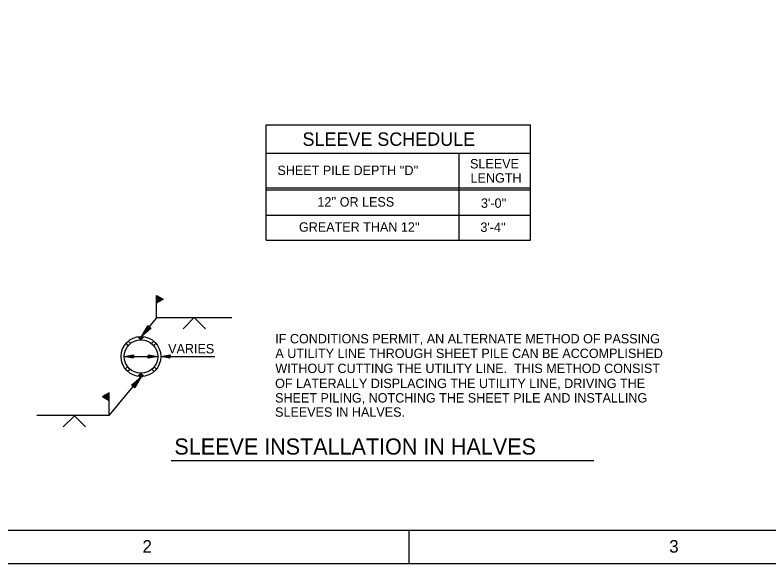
# Model space of a CAD drawing. Extents: x 22339.2 to 22413.4, y 22369.6 to 22418.8.
# Drawn here: x 22369.8 to 22384.77, y 22369.62 to 22380.52 of the extents above; entities that cross this region are included whole.
import ezdxf

# ---------------------------------------------------------------- set-up
doc = ezdxf.new("R2010")
doc.units = 0
for name, color, linetype in [('Level 1', 7, 'Continuous'), ('Level 10', 7, 'Continuous'), ('Level 2', 7, 'Continuous'), ('Level 3', 7, 'Continuous'), ('Level 4', 7, 'Continuous'), ('Level 7', 7, 'Continuous'), ('Level 9', 7, 'Continuous')]:
    doc.layers.add(name, color=color, linetype=linetype)

msp = doc.modelspace()

# ---------------------------------------------------------------- linework, layer by layer
at = {"layer": 'Level 1'}
for p, q in [((22372.31, 22374.139), (22372.31, 22374.139)), ((22372.354, 22374.192), (22372.354, 22374.192)), ((22372.048, 22373.96), (22372.003, 22374.005)), ((22372.093, 22374.003), (22372.048, 22374.048)), ((22372.507, 22374.001), (22372.552, 22374.045)), ((22372.552, 22373.957), (22372.597, 22374.002)), ((22371.965, 22373.741), (22372.632, 22373.741)), ((22371.965, 22373.741), (22371.965, 22373.741)), ((22372.017, 22373.741), (22372.017, 22373.741)), ((22372.58, 22373.741), (22372.58, 22373.741)), ((22372.632, 22373.741), (22372.632, 22373.741)), ((22372.695, 22373.741), (22373.768, 22373.741)), ((22372.695, 22373.741), (22372.695, 22373.741)), ((22372.747, 22373.741), (22372.747, 22373.741)), ((22371.989, 22373.495), (22372.033, 22373.539)), ((22372.032, 22373.449), (22372.076, 22373.493)), ((22372.562, 22373.446), (22372.518, 22373.49)), ((22372.605, 22373.491), (22372.561, 22373.535)), ((22372.301, 22373.339), (22372.301, 22373.339)), ((22372.257, 22373.286), (22372.257, 22373.286))]:
    msp.add_line(p, q, dxfattribs=at)
msp.add_lwpolyline([(22354.719, 22414.965), (22413.386, 22414.965), (22413.386, 22369.621), (22354.719, 22369.621)], close=True, dxfattribs=at)
for points in [[(22372.152, 22373.71), (22371.965, 22373.741), (22372.152, 22373.772), (22372.152, 22373.719), (22372.017, 22373.741), (22372.144, 22373.762), (22372.144, 22373.728), (22372.067, 22373.741), (22372.136, 22373.752), (22372.136, 22373.738), (22372.119, 22373.741)], [(22372.445, 22373.772), (22372.632, 22373.741), (22372.445, 22373.71), (22372.445, 22373.763), (22372.58, 22373.741), (22372.453, 22373.72), (22372.453, 22373.754), (22372.53, 22373.741), (22372.461, 22373.73), (22372.461, 22373.744), (22372.478, 22373.741)], [(22372.882, 22373.71), (22372.695, 22373.741), (22372.882, 22373.772), (22372.882, 22373.719), (22372.747, 22373.741), (22372.874, 22373.762), (22372.874, 22373.728), (22372.797, 22373.741), (22372.866, 22373.752), (22372.866, 22373.738), (22372.849, 22373.741)]]:
    msp.add_lwpolyline(points, dxfattribs=at)
at = {"layer": 'Level 10'}
for p, q in [((22372.611, 22374.504), (22372.611, 22374.954)), ((22372.611, 22374.954), (22372.741, 22374.879)), ((22372.741, 22374.879), (22372.611, 22374.926)), ((22372.741, 22374.879), (22372.611, 22374.901)), ((22372.741, 22374.879), (22372.611, 22374.804)), ((22372.741, 22374.879), (22372.611, 22374.829)), ((22372.741, 22374.879), (22372.614, 22374.85)), ((22372.741, 22374.879), (22372.618, 22374.873)), ((22372.31, 22374.139), (22372.611, 22374.504)), ((22372.607, 22374.513), (22374.107, 22374.513)), ((22373.357, 22374.513), (22373.136, 22374.291)), ((22373.357, 22374.513), (22373.58, 22374.289)), ((22371.668, 22372.57), (22372.301, 22373.339)), ((22371.668, 22373.02), (22371.538, 22372.945)), ((22371.538, 22372.945), (22371.668, 22372.992)), ((22371.538, 22372.945), (22371.668, 22372.966)), ((22371.538, 22372.945), (22371.667, 22372.87)), ((22371.538, 22372.945), (22371.661, 22372.938)), ((22371.538, 22372.945), (22371.665, 22372.915)), ((22371.538, 22372.945), (22371.668, 22372.894)), ((22371.668, 22372.57), (22371.668, 22372.839)), ((22371.668, 22372.57), (22370.229, 22372.57)), ((22370.979, 22372.565), (22370.755, 22372.342)), ((22370.978, 22372.565), (22371.2, 22372.343)), ((22372.897, 22371.676), (22381.297, 22371.676)), ((22377.626, 22369.621), (22377.626, 22370.293))]:
    msp.add_line(p, q, dxfattribs=at)
for points in [[(22372.5, 22374.305), (22372.31, 22374.139), (22372.437, 22374.358), (22372.491, 22374.313), (22372.354, 22374.192), (22372.44, 22374.341), (22372.475, 22374.312), (22372.396, 22374.244), (22372.444, 22374.324), (22372.458, 22374.312), (22372.44, 22374.297)], [(22372.111, 22373.173), (22372.301, 22373.339), (22372.175, 22373.12), (22372.12, 22373.165), (22372.257, 22373.286), (22372.171, 22373.137), (22372.136, 22373.166), (22372.215, 22373.234), (22372.168, 22373.154), (22372.153, 22373.166), (22372.171, 22373.181)]]:
    msp.add_lwpolyline(points, dxfattribs=at)
at = {"layer": 'Level 2'}
for p, q in [((22374.787, 22377.094), (22380.037, 22377.094)), ((22374.787, 22377.052), (22380.037, 22377.052)), ((22374.787, 22376.552), (22380.037, 22376.552)), ((22372.299, 22374.074), (22372.24, 22374.133)), ((22372.299, 22374.074), (22372.357, 22374.133)), ((22372.299, 22373.408), (22372.24, 22373.35)), ((22372.299, 22373.408), (22372.357, 22373.35))]:
    msp.add_line(p, q, dxfattribs=at)
for points in [[(22372.242, 22374.132), (22372.356, 22374.132)], [(22372.252, 22374.121), (22372.345, 22374.121)], [(22372.262, 22374.111), (22372.335, 22374.111)], [(22372.273, 22374.1), (22372.325, 22374.1)], [(22372.283, 22374.09), (22372.314, 22374.09)], [(22372.294, 22374.08), (22372.304, 22374.08)], [(22372.249, 22373.358), (22372.349, 22373.358)], [(22372.259, 22373.368), (22372.338, 22373.368)], [(22372.261, 22373.347), (22372.338, 22373.347)], [(22372.269, 22373.379), (22372.328, 22373.379)], [(22372.28, 22373.389), (22372.317, 22373.389)], [(22372.29, 22373.399), (22372.307, 22373.399)]]:
    msp.add_lwpolyline(points, dxfattribs=at)
for radius in [0.396, 0.333]:
    msp.add_circle((22372.299, 22373.741), radius, dxfattribs=at)
at = {"layer": 'Level 3'}
for p, q in [((22372.299, 22374.074), (22372.299, 22374.074)), ((22372.299, 22373.741), (22372.299, 22373.741))]:
    msp.add_line(p, q, dxfattribs=at)
at = {"layer": 'Level 4'}
msp.add_line((22371.668, 22372.839), (22371.668, 22373.02), dxfattribs=at)
at = {"layer": 'Level 7'}
for p, q in [((22374.787, 22378.345), (22380.037, 22378.345)), ((22374.787, 22376.052), (22374.787, 22378.345)), ((22380.037, 22376.052), (22380.037, 22378.345)), ((22374.787, 22377.783), (22380.037, 22377.783)), ((22378.621, 22376.052), (22378.621, 22377.783)), ((22374.787, 22376.052), (22380.037, 22376.052)), ((22373.358, 22374.513), (22373.357, 22374.513)), ((22370.978, 22372.565), (22370.978, 22372.565))]:
    msp.add_line(p, q, dxfattribs=at)
at = {"layer": 'Level 9'}
msp.add_line((22356.719, 22370.293), (22409.05, 22370.293), dxfattribs=at)

# ---------------------------------------------------------------- texts
at = {"layer": 'Level 1'}
for s, p in [('2', (22372.33, 22369.845)), ('3', (22382.794, 22369.845))]:
    msp.add_text(s, height=0.25, dxfattribs=at).set_placement(p)
at = {"layer": 'Level 3'}
msp.add_text('SLEEVE INSTALLATION IN HALVES', height=0.32, dxfattribs=at).set_placement((22372.963, 22371.793))
at = {"layer": 'Level 4'}
for s, height, p in [('SLEEVE SCHEDULE', 0.2667, (22375.508, 22377.926)), ('SLEEVE', 0.1867, (22378.837, 22377.477)), ("SHEET PILE DEPTH ''D''", 0.1867, (22375.01, 22377.346)), ('LENGTH', 0.1867, (22378.847, 22377.196)), ("12'' OR LESS", 0.1867, (22375.805, 22376.72)), ("3'-0''", 0.1867, (22379.054, 22376.695)), ("GREATER THAN 12''", 0.1867, (22375.438, 22376.22)), ("3'-4''", 0.1867, (22379.042, 22376.216)), ('IF CONDITIONS PERMIT, AN ALTERNATE METHOD OF PASSING', 0.18667, (22374.967, 22374.002)), ('VARIES', 0.1867, (22372.839, 22373.803)), ('A UTILITY LINE THROUGH SHEET PILE CAN BE ACCOMPLISHED', 0.18667, (22374.969, 22373.711)), ('WITHOUT CUTTING THE UTILITY LINE.  THIS METHOD CONSIST', 0.18667, (22374.969, 22373.413)), ('OF LATERALLY DISPLACING THE UTILITY LINE, DRIVING THE', 0.18667, (22374.964, 22373.114)), ('SHEET PILING, NOTCHING THE SHEET PILE AND INSTALLING', 0.18667, (22374.964, 22372.827)), ('SLEEVES IN HALVES.', 0.18667, (22374.964, 22372.545))]:
    msp.add_text(s, height=height, dxfattribs=at).set_placement(p)

doc.saveas('drawing.dxf')
